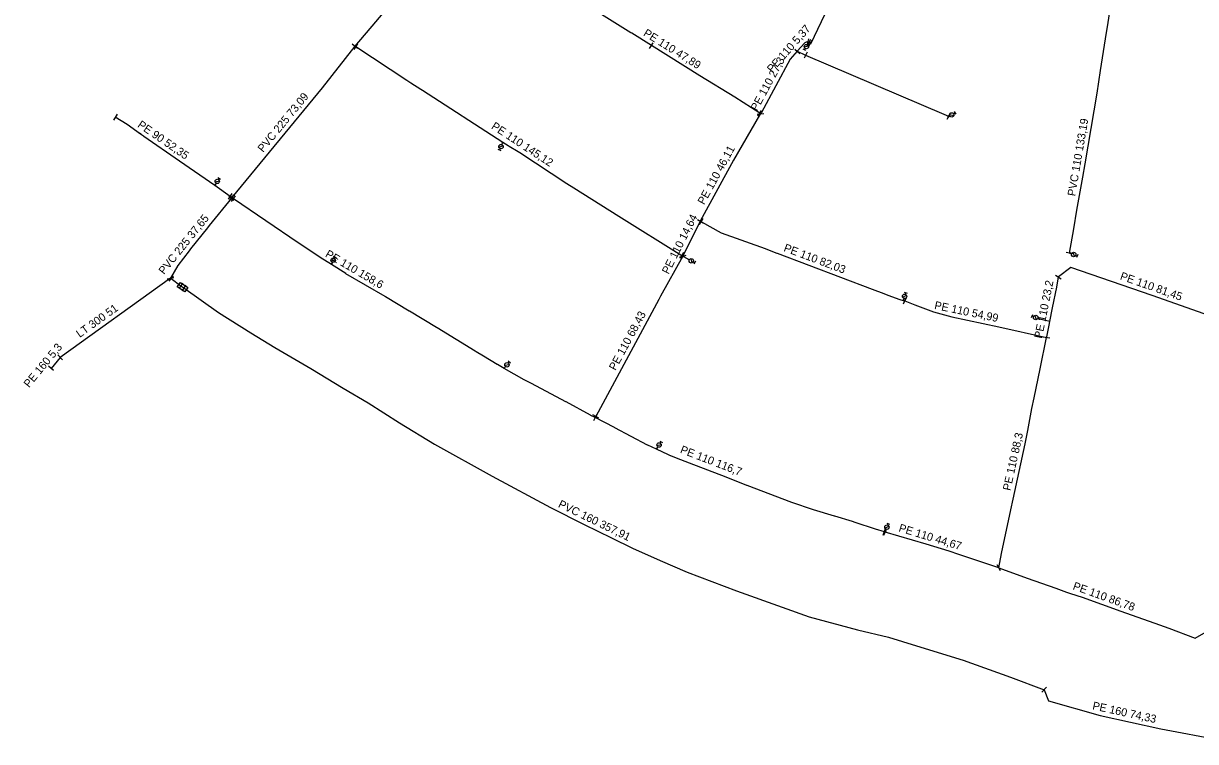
# Model space of a CAD drawing. Extents: x -736619 to -735426, y -1033122 to -1031044.
# Drawn here: x -736288.7 to -735849.4, y -1033001 to -1032731.9 of the extents above; entities that cross this region are included whole.
import ezdxf

# ---------------------------------------------------------------- set-up
doc = ezdxf.new("R2010")
doc.units = 0
for name, color, linetype in [('Vrstva 1', 7, 'Continuous'), ('Vrstva 17', 7, 'Continuous'), ('Vrstva 25', 7, 'Continuous'), ('Vrstva 29', 7, 'Continuous'), ('Vrstva 63', 7, 'Continuous')]:
    doc.layers.add(name, color=color, linetype=linetype)

# ---------------------------------------------------------------- blocks, each defined once
blk = doc.blocks.new('100')
at = {"layer": 'Vrstva 1'}
blk.add_circle((0, 0), 0.127, dxfattribs=at)
blk = doc.blocks.new('133')
at = {"layer": 'Vrstva 1'}
for p, q in [((0.28, 0), (0, 0)), ((0.54, 0.58), (1.7, -0.58)), ((1.94, 0), (2.52, 0)), ((2.52, 0.58), (2.52, -0.58))]:
    blk.add_line(p, q, dxfattribs=at)
blk.add_circle((1.105, 0.003), 0.825, dxfattribs=at)
blk = doc.blocks.new('147')
at = {"layer": 'Vrstva 1'}
blk.add_line((0, 1.27), (0, -1.27), dxfattribs=at)

msp = doc.modelspace()

# ---------------------------------------------------------------- linework, layer by layer
at = {"layer": 'Vrstva 17'}
for p, q in [((-736125.507, -1032694.196), (-736164.447, -1032740.408)), ((-736164.447, -1032740.408), (-736164.154, -1032740.581)), ((-735998.653, -1032742.322), (-735995.557, -1032743.741)), ((-735994.335, -1032739.07), (-735994.795, -1032738.864)), ((-735993.808, -1032739.322), (-735994.335, -1032739.07)), ((-736210.532, -1032797.133), (-736211.124, -1032796.691)), ((-736210.532, -1032797.133), (-736210.739, -1032797.41)), ((-736209.949, -1032797.568), (-736210.532, -1032797.133)), ((-736034.994, -1032805.976), (-736041.562, -1032819.055)), ((-736034.994, -1032805.976), (-736034.721, -1032806.125)), ((-736041.961, -1032818.853), (-736041.562, -1032819.055)), ((-736233.526, -1032827.316), (-736274.943, -1032857.073)), ((-736233.346, -1032827.454), (-736233.526, -1032827.316)), ((-736233.346, -1032827.454), (-736229.65, -1032830.27)), ((-736229.65, -1032830.27), (-736228.54, -1032831.02)), ((-736274.943, -1032857.073), (-736278.316, -1032861.158)), ((-736074.139, -1032879.232), (-736074.356, -1032879.63)), ((-735965.679, -1032922.509), (-735966.035, -1032922.402))]:
    msp.add_line(p, q, dxfattribs=at)
for points in [[(-735993.808, -1032739.322), (-735993.552, -1032739.478), (-735957.374, -1032663.621), (-735952.591, -1032654.188), (-735942.348, -1032634.305), (-735933.918, -1032619.842)], [(-735896.6, -1032817.99), (-735895.02, -1032808.86), (-735893.86, -1032801.88), (-735891.68, -1032789.5), (-735890.79, -1032784.47), (-735886.29, -1032757.99), (-735885.01, -1032749.55), (-735882.73, -1032735.25), (-735882.27, -1032732.42), (-735880.96, -1032723.07), (-735880.62, -1032711.86), (-735880.51, -1032707.38), (-735880.24, -1032696.67), (-735880.35, -1032686.61), (-735880.26, -1032686.1)], [(-736053.341, -1032740.177), (-736060.689, -1032735.583), (-736061.081, -1032735.355), (-736087.044, -1032719.018), (-736087.511, -1032718.722), (-736112.832, -1032702.648), (-736113.092, -1032702.546), (-736117.604, -1032699.702)], [(-736164.447, -1032740.408), (-736176.739, -1032755.992), (-736210.532, -1032797.133)], [(-736164.154, -1032740.581), (-736144.925, -1032753.1), (-736143.424, -1032754.098), (-736139.691, -1032756.525), (-736139.06, -1032756.915), (-736109.001, -1032776.411), (-736106.944, -1032777.668), (-736106.655, -1032777.849), (-736103.32, -1032779.829), (-736102.585, -1032780.272), (-736085.011, -1032791.844), (-736082.437, -1032793.462), (-736065.503, -1032804.163), (-736041.961, -1032818.853)], [(-736012.736, -1032765.563), (-736022.115, -1032759.464), (-736035.214, -1032751.511), (-736053.341, -1032740.177)], [(-735998.653, -1032742.322), (-736001.298, -1032745.313), (-736012.065, -1032765.266), (-736012.446, -1032765.768)], [(-735994.795, -1032738.864), (-735995.293, -1032738.848), (-735995.8, -1032739.096), (-735998.653, -1032742.322)], [(-735995.557, -1032743.741), (-735943.725, -1032765.929), (-735942.01, -1032766.69)], [(-736211.124, -1032796.691), (-736216.969, -1032792.647), (-736230.201, -1032783.444), (-736243.523, -1032774.273), (-736243.706, -1032774.146), (-736244.824, -1032773.388), (-736249.822, -1032769.815), (-736254.246, -1032767.011)], [(-736012.446, -1032765.768), (-736012.834, -1032766.242), (-736022.545, -1032783.177), (-736034.994, -1032805.976)], [(-736012.736, -1032765.563), (-736012.467, -1032765.753), (-736012.446, -1032765.768)], [(-736210.739, -1032797.41), (-736219.01, -1032807.639), (-736219.718, -1032808.522), (-736225.999, -1032816.354), (-736226.56, -1032817.07), (-736230.818, -1032822.576), (-736233.526, -1032827.316)], [(-736074.356, -1032879.63), (-736075.975, -1032878.796), (-736076.131, -1032878.715), (-736085.321, -1032873.761), (-736085.395, -1032873.721), (-736098.323, -1032866.889), (-736100.7, -1032865.632), (-736100.957, -1032865.497), (-736108.529, -1032861.191), (-736111.017, -1032859.776), (-736111.135, -1032859.709), (-736116.225, -1032856.645), (-736119.031, -1032854.955), (-736119.432, -1032854.709), (-736133.632, -1032846.004), (-736133.868, -1032845.861), (-736143.933, -1032839.763), (-736144.063, -1032839.684), (-736153.014, -1032834.339), (-736153.122, -1032834.274), (-736167.804, -1032825.679), (-736167.842, -1032825.657), (-736173.268, -1032822.217), (-736177.403, -1032819.596), (-736177.604, -1032819.468), (-736185.657, -1032814.11), (-736185.743, -1032814.053), (-736209.949, -1032797.568)], [(-736034.721, -1032806.125), (-736034.512, -1032806.253), (-736027.221, -1032810.321), (-736010.756, -1032816.237), (-736010.442, -1032816.356), (-736006.375, -1032817.957), (-736006.161, -1032818.041), (-735970.559, -1032831.439), (-735966.182, -1032833.083), (-735964.697, -1032833.677), (-735960.222, -1032835.324), (-735958.929, -1032835.701), (-735958.563, -1032835.835), (-735958.385, -1032835.9)], [(-736041.562, -1032819.055), (-736049.95, -1032834.155), (-736050.548, -1032835.361), (-736074.139, -1032879.232)], [(-735824.887, -1032848.661), (-735841.901, -1032842.172), (-735865.619, -1032833.808), (-735896.141, -1032823.373), (-735900.799, -1032826.89)], [(-735905.223, -1032849.553), (-735905.204, -1032849.364), (-735904.266, -1032844.997), (-735904.034, -1032843.624), (-735903.009, -1032838.527), (-735901.431, -1032830.692), (-735900.799, -1032826.89)], [(-736228.54, -1032831.02), (-736215.59, -1032840.24), (-736203.45, -1032847.8), (-736194.41, -1032853.3), (-736180.99, -1032861.27), (-736168.8, -1032868.56), (-736159.53, -1032874.03), (-736147.68, -1032881.55), (-736134.59, -1032889.54), (-736113.02, -1032901.51), (-736091.13, -1032913.35), (-736078.5, -1032919.7), (-736068.24, -1032924.7), (-736060.45, -1032928.57), (-736050.04, -1032933.18), (-736039.92, -1032937.57), (-736021.43, -1032944.49), (-736004.32, -1032950.66), (-735994.17, -1032954.34), (-735976.08, -1032959.18), (-735964.53, -1032961.92), (-735953.96, -1032965.14), (-735936.53, -1032970.58), (-735918.76, -1032976.88), (-735906.132, -1032981.597)], [(-735958.385, -1032835.9), (-735954.551, -1032837.303), (-735947.651, -1032840.025), (-735940.701, -1032841.903), (-735923.179, -1032845.553), (-735905.223, -1032849.553)], [(-735923.085, -1032935.961), (-735922.146, -1032930.594), (-735918.603, -1032914.235), (-735917.81, -1032910.242), (-735913.243, -1032889.447), (-735912.311, -1032884.464), (-735910.704, -1032876.268), (-735909.892, -1032872.168), (-735907.596, -1032861.357), (-735905.223, -1032849.553)], [(-735966.035, -1032922.402), (-735969.398, -1032921.438), (-735976.968, -1032918.921), (-735978.029, -1032918.601), (-735984.613, -1032916.619), (-735984.727, -1032916.585), (-735992.642, -1032914.141), (-736000.707, -1032911.45), (-736000.742, -1032911.437), (-736017.497, -1032905.035), (-736017.533, -1032905.021), (-736025.276, -1032901.965), (-736039.047, -1032896.659), (-736043.982, -1032894.761), (-736046.053, -1032893.965), (-736046.227, -1032893.898), (-736046.958, -1032893.556), (-736051.379, -1032891.485), (-736054.726, -1032889.916), (-736054.76, -1032889.9), (-736067.03, -1032883.412), (-736067.195, -1032883.324), (-736074.356, -1032879.63)], [(-735923.085, -1032935.961), (-735938.104, -1032930.878), (-735941.688, -1032929.742), (-735950.304, -1032927.115), (-735965.679, -1032922.509)], [(-735923.085, -1032935.961), (-735912.553, -1032939.774), (-735901.778, -1032943.523), (-735897.73, -1032945.001), (-735896.257, -1032945.501), (-735891.938, -1032946.964), (-735877.445, -1032952.202), (-735862.92, -1032957.268), (-735859.475, -1032958.573), (-735849.559, -1032962.291), (-735844.541, -1032959.401), (-735844.539, -1032959.4), (-735841.934, -1032958.161)], [(-735906.132, -1032981.597), (-735904.521, -1032985.822), (-735885.141, -1032991.258), (-735862.403, -1032996.233), (-735839.791, -1033000.528), (-735836.438, -1033001.046)]]:
    msp.add_lwpolyline(points, dxfattribs=at)
at = {"layer": 'Vrstva 25'}
msp.add_lwpolyline([(-736229.83, -1032828.92), (-736227.01, -1032830.86), (-736228.14, -1032832.51), (-736231.05, -1032830.6), (-736229.83, -1032828.92)], dxfattribs=at)
at = {"layer": 'Vrstva 63'}
for points in [[(-735994.335, -1032739.07), (-735994.448, -1032739.305), (-735994.649, -1032739.633)], [(-735942.01, -1032766.69), (-735942.057, -1032766.926), (-735941.728, -1032766.727)], [(-736244.824, -1032773.388), (-736244.758, -1032773.301), (-736245.219, -1032772.959)], [(-736109.001, -1032776.411), (-736109.162, -1032776.704), (-736109.285, -1032777.022)], [(-736216.969, -1032792.647), (-736216.764, -1032792.349), (-736216.586, -1032792.05)], [(-736041.562, -1032819.055), (-736041.253, -1032819.283), (-736039.35, -1032820.302)], [(-735896.6, -1032817.99), (-735896.33, -1032817.95), (-735896.14, -1032818.01)], [(-736173.268, -1032822.217), (-736173.193, -1032822.098), (-736173.011, -1032821.672)], [(-735958.929, -1032835.701), (-735958.864, -1032835.559), (-735958.761, -1032835.223)], [(-735904.034, -1032843.624), (-735907.942, -1032842.685), (-735908.265, -1032842.567)], [(-736108.529, -1032861.191), (-736108.443, -1032861.039), (-736108.169, -1032860.702)], [(-736051.379, -1032891.485), (-736051.196, -1032891.094), (-736051.037, -1032890.835)], [(-735965.679, -1032922.509), (-735965.582, -1032922.186), (-735965.417, -1032921.719)]]:
    msp.add_lwpolyline(points, dxfattribs=at)

# ---------------------------------------------------------------- block references
at = {"layer": 'Vrstva 25'}
for p, xscale, yscale, rotation in [((-735994.649, -1032739.633), 0.9999999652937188, 0.9999999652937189, -121.99999738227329), ((-735941.728, -1032766.727), 0.9999999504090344, 0.9999999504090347, 31.000001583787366), ((-736109.285, -1032777.022), 0.9999999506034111, 0.9999999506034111, -112.00000028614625), ((-736216.586, -1032792.05), 0.9999999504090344, 0.9999999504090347, 58.99999841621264), ((-736173.011, -1032821.672), 0.9999999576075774, 0.9999999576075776, 66.99999911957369), ((-736039.35, -1032820.302), 1.0037041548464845, 1.0037041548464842, -29.379208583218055), ((-735896.14, -1032818.01), 1.0316957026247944, 1.0316957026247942, -23.584588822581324), ((-735958.761, -1032835.223), 0.9999999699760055, 0.9999999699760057, 73.00000033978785), ((-735908.265, -1032842.567), 1.0296949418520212, 1.0296949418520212, 155.86621099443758), ((-736108.169, -1032860.702), 0.9999999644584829, 0.999999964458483, 50.999998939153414), ((-736051.037, -1032890.835), 0.9999999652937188, 0.9999999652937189, 58.00000261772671), ((-735965.417, -1032921.719), 0.9999999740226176, 0.9999999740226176, 71.00000039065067)]:
    msp.add_blockref('133', p, dxfattribs=dict(at, xscale=xscale, yscale=yscale, rotation=rotation))
at = {"layer": 'Vrstva 29'}
for p, xscale, yscale, rotation in [((-735994.795, -1032738.864), 1.0009847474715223, 1.0009847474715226, -14.22432628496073), ((-735994.335, -1032739.07), 1.0138864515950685, 1.0138864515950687, -27.5653151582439), ((-736164.447, -1032740.408), 0.9999999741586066, 0.9999999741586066, -129.99999870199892), ((-736164.154, -1032740.581), 0.9999999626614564, 0.9999999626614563, -32.99999840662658), ((-736053.341, -1032740.177), 0.9999999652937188, 0.9999999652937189, 148.0000026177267), ((-735998.653, -1032742.322), 0.9999999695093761, 0.9999999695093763, 48.99999865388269), ((-735993.808, -1032739.322), 1.0037041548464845, 1.0037041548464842, -29.379208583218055), ((-735995.557, -1032743.741), 1.0169561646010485, 1.0169561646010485, -26.97601647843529), ((-736254.246, -1032767.011), 0.9999999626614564, 0.9999999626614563, -32.99999840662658), ((-736012.446, -1032765.768), 0.9999999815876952, 0.9999999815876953, 97.99999954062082), ((-736012.736, -1032765.563), 0.9999999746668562, 0.999999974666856, 145.99999954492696), ((-735942.01, -1032766.69), 1.0169561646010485, 1.0169561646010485, -26.97601647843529), ((-736211.124, -1032796.691), 0.9999999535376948, 0.9999999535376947, 143.99999865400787), ((-736210.739, -1032797.41), 0.9999999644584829, 0.999999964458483, -129.00000106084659), ((-736210.532, -1032797.133), 0.9999999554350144, 0.9999999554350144, 143.00000079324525), ((-736209.949, -1032797.568), 0.9999999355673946, 0.9999999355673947, 145.00000060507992), ((-736034.994, -1032805.976), 0.9999999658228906, 0.9999999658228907, 62.00000017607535), ((-736034.721, -1032806.125), 0.9999999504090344, 0.9999999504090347, -31.000001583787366), ((-736041.562, -1032819.055), 0.9999999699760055, 0.9999999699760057, 106.99999966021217), ((-736041.961, -1032818.853), 0.9999999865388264, 0.9999999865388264, -30.00000044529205), ((-735896.6, -1032817.99), 0.9999999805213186, 0.9999999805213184, -100.99999941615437), ((-736233.526, -1032827.316), 0.9999999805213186, 0.9999999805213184, 100.99999941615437), ((-736233.346, -1032827.454), 0.9999999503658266, 0.9999999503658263, -37.999999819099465), ((-736229.65, -1032830.27), 0.9999999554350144, 0.9999999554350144, -36.99999920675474), ((-736228.54, -1032831.02), 0.9999999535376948, 0.9999999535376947, -36.000001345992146), ((-735900.799, -1032826.89), 0.9999999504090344, 0.9999999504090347, 58.99999841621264), ((-735958.385, -1032835.9), 1.0275072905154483, 1.027507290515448, -24.689105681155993), ((-735905.223, -1032849.553), 0.9999999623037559, 0.999999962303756, 80.99999986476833), ((-736274.943, -1032857.073), 0.9999999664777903, 0.9999999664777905, 42.999998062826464), ((-736278.316, -1032861.158), 0.9999999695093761, 0.9999999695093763, -131.00000134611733), ((-736074.139, -1032879.232), 0.999999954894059, 0.9999999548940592, -119.00000058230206), ((-736074.356, -1032879.63), 1.0106517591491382, 1.010651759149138, 151.83788415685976), ((-735966.035, -1032922.402), 1.0365458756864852, 1.0365458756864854, 158.02850914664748), ((-735965.679, -1032922.509), 1.035124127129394, 1.0351241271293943, 157.49634583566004), ((-735923.085, -1032935.961), 0.9999999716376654, 0.9999999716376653, -150.00000103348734), ((-735906.132, -1032981.597), 0.9999999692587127, 0.9999999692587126, -46.00000080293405)]:
    msp.add_blockref('147', p, dxfattribs=dict(at, xscale=xscale, yscale=yscale, rotation=rotation))
at = {"layer": 'Vrstva 63'}
for p, xscale, yscale, rotation in [((-735994.448, -1032739.305), 0.9999999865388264, 0.9999999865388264, -120.00000044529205), ((-735942.057, -1032766.926), 0.9999999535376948, 0.9999999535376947, -36.000001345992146), ((-736244.758, -1032773.301), 1.000191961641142, 1.000191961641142, -82.91099886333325), ((-736109.162, -1032776.704), 0.9999999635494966, 0.9999999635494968, 65.00000039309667), ((-736216.764, -1032792.349), 0.9999999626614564, 0.9999999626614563, 57.00000159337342), ((-736041.253, -1032819.283), 0.9999999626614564, 0.9999999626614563, -32.99999840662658), ((-735896.33, -1032817.95), 1.0011216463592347, 1.0011216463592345, -6.5826102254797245), ((-736173.193, -1032822.098), 0.9999999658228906, 0.9999999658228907, 62.00000017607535), ((-735958.864, -1032835.559), 0.999999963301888, 0.9999999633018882, 69.00000101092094), ((-735907.942, -1032842.685), 1.0335064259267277, 1.033506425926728, -23.04128150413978), ((-736108.443, -1032861.039), 0.9999999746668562, 0.999999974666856, 55.999999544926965), ((-736051.196, -1032891.093), 0.9999999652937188, 0.9999999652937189, 58.00000261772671), ((-735965.582, -1032922.186), 0.9999999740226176, 0.9999999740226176, 71.00000039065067)]:
    msp.add_blockref('100', p, dxfattribs=dict(at, xscale=xscale, yscale=yscale, rotation=rotation))

# ---------------------------------------------------------------- texts
for s, height, rotation, p in [('PE 110 5,37', 2.99999, 48.51, (-736008.087, -1032750.574)), ('PE 110 47,89', 2.99999, 327.98, (-736056.594, -1032736.253)), ('PE 110 27,3', 2.99999, 61.65, (-736013.711, -1032764.949)), ('PVC 225 73,09', 2.99999, 50.6, (-736198.863, -1032780.406)), ('PE 90 52,35', 2.99999, 325.46, (-736246.16, -1032770.514)), ('PE 110 145,12', 2.99999, 326.64, (-736113.576, -1032771.11)), ('PVC 110 133,19', 2.99999, 80.36, (-735894.506, -1032796.79)), ('PE 110 46,11', 2.99999, 61.36, (-736033.582, -1032800.049)), ('PVC 225 37,65', 2.99999, 51.27, (-736235.957, -1032826.213)), ('PE 110 14,64', 2.99999, 63.34, (-736046.891, -1032826.1)), ('PE 110 158,6', 2.99999, 329.66, (-736175.802, -1032819.141)), ('PE 110 82,03', 2.99999, 339.38, (-736003.991, -1032817.146)), ('PE 110 81,45', 2.99999, 340.58, (-735877.941, -1032827.766)), ('PE 110 23,2', 2.99999, 78.61, (-735906.983, -1032850.157)), ('LT 300 51', 3, 35.7, (-736267.562, -1032849.801)), ('PE 110 54,99', 2.99999, 348.23, (-735947.472, -1032838.857)), ('PE 110 68,43', 2.99999, 61.73, (-736066.793, -1032862.191)), ('PE 160 5,3', 3, 50.45, (-736286.55, -1032868.617)), ('PE 110 88,3', 2.99999, 77.61, (-735918.78, -1032907.195)), ('PE 110 116,7', 2.99999, 338.93, (-736042.787, -1032892.758)), ('PVC 160 357,91', 2.99999, 334.02, (-736088.51, -1032913.042)), ('PE 110 44,67', 2.99999, 343.04, (-735960.875, -1032922.218)), ('PE 110 86,78', 2.99999, 340.13, (-735895.64, -1032943.924)), ('PE 160 74,33', 2.99999, 347.66, (-735888.241, -1032988.941))]:
    msp.add_text(s, height=height, rotation=rotation, dxfattribs=at).set_placement(p)

doc.saveas('drawing.dxf')
